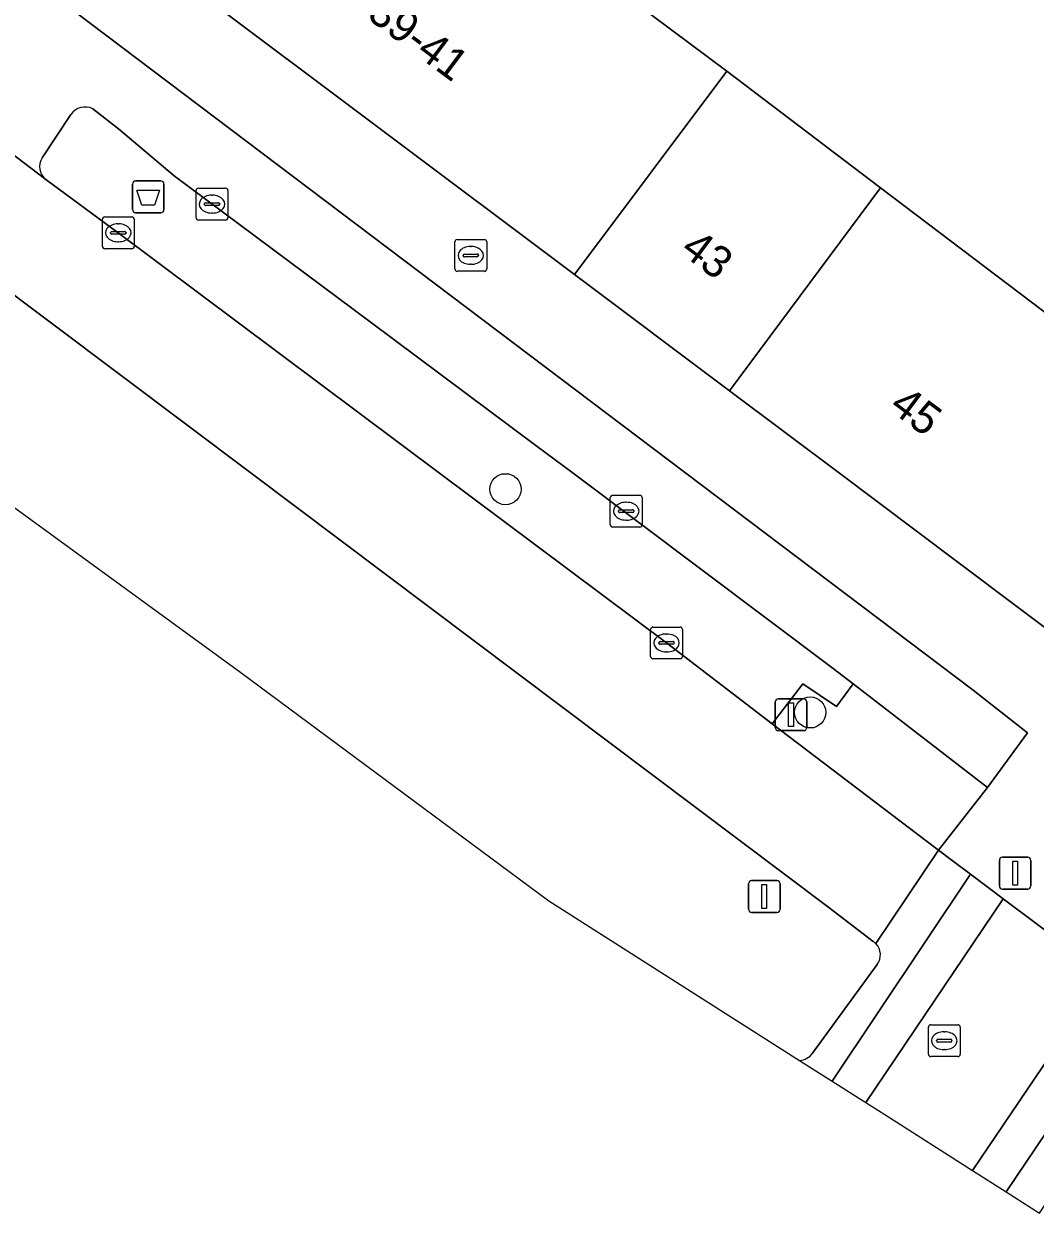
# Model space of a CAD drawing. Extents: x 161087 to 161926, y 382572 to 383873.
# Drawn here: x 161120.79 to 161152.56, y 383226.76 to 383264.12 of the extents above; entities that cross this region are included whole.
import ezdxf

# ---------------------------------------------------------------- set-up
doc = ezdxf.new("R2010")
doc.units = 0
for name, color, linetype in [('IMGEO_Afvalbak', 7, 'Continuous'), ('IMGEO_Berm_groen', 7, 'Continuous'), ('IMGEO_Berm_open', 7, 'Continuous'), ('IMGEO_Boom', 7, 'Continuous'), ('IMGEO_Brandkraan', 7, 'Continuous'), ('IMGEO_Fietspad_gesloten', 7, 'Continuous'), ('IMGEO_Kolk', 7, 'Continuous'), ('IMGEO_Lichtmast', 7, 'Continuous'), ('IMGEO_OVBaan_gesloten', 7, 'Continuous'), ('IMGEO_Pand', 7, 'Continuous'), ('IMGEO_Pand_nummerreeks', 7, 'Continuous'), ('IMGEO_Rijbaan_lokaal_gesloten', 7, 'Continuous'), ('IMGEO_Rijbaan_lokaal_open', 7, 'Continuous'), ('IMGEO_Rioolput', 7, 'Continuous'), ('IMGEO_Verkeerseiland_groen', 7, 'Continuous'), ('IMGEO_Verkeersregelinstallatiepaal', 7, 'Continuous'), ('IMGEO_Voetgangersgebied_open', 7, 'Continuous')]:
    doc.layers.add(name, color=color, linetype=linetype)

msp = doc.modelspace()

# ---------------------------------------------------------------- linework, layer by layer
at = {"layer": 'IMGEO_Afvalbak'}
for p, q in [((161124.206, 383258.282), (161124.206, 383259.082)), ((161124.206, 383259.082), (161124.206, 383258.282)), ((161124.306, 383259.182), (161125.096, 383259.182)), ((161125.096, 383259.182), (161124.306, 383259.182)), ((161125.196, 383259.082), (161125.196, 383258.282)), ((161125.196, 383258.282), (161125.196, 383259.082)), ((161125.096, 383258.182), (161124.306, 383258.182)), ((161124.306, 383258.182), (161125.096, 383258.182))]:
    msp.add_line(p, q, dxfattribs=at)
msp.add_lwpolyline([(161124.349, 383258.896), (161125.053, 383258.896), (161124.904, 383258.426), (161124.498, 383258.426), (161124.349, 383258.896)], dxfattribs=at)
for centre, start, end in [((161124.306, 383259.082), 90, 180), ((161124.306, 383259.082), 90, 180), ((161125.096, 383259.082), 0, 90), ((161125.096, 383259.082), 360, 90), ((161124.306, 383258.282), 180, 270), ((161124.306, 383258.282), 180, 270), ((161125.096, 383258.282), 270, 0), ((161125.096, 383258.282), 270, 0)]:
    msp.add_arc(centre, 0.1, start, end, dxfattribs=at)
at = {"layer": 'IMGEO_Berm_groen'}
msp.add_lwpolyline([(161146.845, 383243.381), (161146.322, 383242.671), (161145.266, 383243.39), (161144.303, 383242.133), (161149.136, 383238.449), (161149.525, 383238.158), (161151.057, 383240.133)], close=True, dxfattribs=at)
at = {"layer": 'IMGEO_Berm_open'}
for points in [[(161122.272, 383261.268), (161121.372, 383259.911)], [(161138.045, 383250), (161136.923, 383250.842), (161131.675, 383254.752), (161125.515, 383259.342), (161123.772, 383260.815), (161122.964, 383261.452)], [(161121.486, 383259.231), (161123.758, 383257.552), (161133.852, 383250), (161140.977, 383244.669), (161144.303, 383242.133), (161145.266, 383243.39), (161146.322, 383242.671), (161146.845, 383243.381), (161146.169, 383243.902), (161138.045, 383250)]]:
    msp.add_lwpolyline(points, dxfattribs=at)
for centre, radius, start, end in [((161122.728, 383260.947), 0.557, 64.9073, 144.8731), ((161121.801, 383259.633), 0.511, 147.0872, 231.9467)]:
    msp.add_arc(centre, radius, start, end, dxfattribs=at)
at = {"layer": 'IMGEO_Boom'}
for centre in [(161135.922, 383249.498), (161145.494, 383242.487)]:
    msp.add_circle(centre, 0.489, dxfattribs=at)
at = {"layer": 'IMGEO_Brandkraan'}
for p, q in [((161134.332, 383256.417), (161134.332, 383257.269)), ((161134.407, 383257.343), (161135.259, 383257.343)), ((161135.333, 383257.269), (161135.333, 383256.417)), ((161134.591, 383256.837), (161134.591, 383256.849)), ((161135.029, 383256.8), (161134.631, 383256.8)), ((161134.634, 383256.886), (161135.032, 383256.886)), ((161134.82, 383257.123), (161134.845, 383257.123)), ((161135.075, 383256.849), (161135.075, 383256.837)), ((161134.843, 383256.563), (161134.818, 383256.563)), ((161135.259, 383256.343), (161134.407, 383256.343))]:
    msp.add_line(p, q, dxfattribs=at)
for points in [[(161134.332, 383256.417), (161134.332, 383257.269)], [(161134.407, 383257.343), (161135.259, 383257.343)], [(161135.333, 383257.269), (161135.333, 383256.417)], [(161135.259, 383256.343), (161134.407, 383256.343)]]:
    msp.add_lwpolyline(points, dxfattribs=at)
for centre, radius, start, end in [((161134.409, 383257.267), 0.0765, 91.552, 178.448), ((161134.409, 383257.267), 0.0765, 91.552, 178.448), ((161135.257, 383257.267), 0.0765, 1.552, 88.448), ((161135.257, 383257.267), 0.0765, 1.552, 88.448), ((161134.631, 383256.846), 0.0403, 85.8775, 175.7526), ((161134.628, 383256.836), 0.0366, 178.938, 274.7102), ((161135.032, 383256.843), 0.043, 264.8664, 352.4533), ((161135.036, 383256.848), 0.0386, 1.7309, 96.639), ((161134.409, 383256.419), 0.0765, 181.552, 268.448), ((161134.409, 383256.419), 0.0765, 181.552, 268.448), ((161135.257, 383256.419), 0.0765, 271.552, 358.448), ((161135.257, 383256.419), 0.0765, 271.552, 358.448)]:
    msp.add_arc(centre, radius, start, end, dxfattribs=at)
for centre, major_axis, ratio, start_param, end_param in [((161134.819, 383256.843), (-0.387, 0.002), 0.722429, 4.712389, 7.853982), ((161134.844, 383256.843), (-0.39, 0.002), 0.717154, 1.570796, 4.712389)]:
    msp.add_ellipse(centre, major_axis=major_axis, ratio=ratio, start_param=start_param, end_param=end_param, dxfattribs=at)
at = {"layer": 'IMGEO_Fietspad_gesloten'}
for points in [[(161122.964, 383261.452), (161123.772, 383260.815), (161125.515, 383259.342), (161131.675, 383254.752), (161136.923, 383250.842), (161138.045, 383250), (161146.169, 383243.902), (161146.845, 383243.381), (161151.057, 383240.133), (161152.322, 383241.841), (161150.612, 383243.184), (161141.59, 383250), (161122.381, 383264.513)], [(161118.752, 383261.298), (161121.486, 383259.231)], [(161121.372, 383259.911), (161122.272, 383261.268)]]:
    msp.add_lwpolyline(points, dxfattribs=at)
for centre, radius, start, end in [((161122.728, 383260.947), 0.557, 64.9073, 144.8731), ((161121.801, 383259.633), 0.511, 147.0872, 231.9467)]:
    msp.add_arc(centre, radius, start, end, dxfattribs=at)
at = {"layer": 'IMGEO_Kolk'}
for p, q in [((161126.205, 383258.028), (161126.205, 383258.88)), ((161126.28, 383258.954), (161127.132, 383258.954)), ((161126.693, 383258.734), (161126.718, 383258.734)), ((161127.206, 383258.88), (161127.206, 383258.028)), ((161126.464, 383258.448), (161126.464, 383258.46)), ((161126.902, 383258.411), (161126.504, 383258.411)), ((161126.507, 383258.497), (161126.905, 383258.497)), ((161126.948, 383258.46), (161126.948, 383258.448)), ((161123.262, 383257.127), (161123.262, 383257.979)), ((161123.337, 383258.053), (161124.189, 383258.053)), ((161124.263, 383257.979), (161124.263, 383257.127)), ((161127.132, 383257.954), (161126.28, 383257.954)), ((161126.716, 383258.174), (161126.691, 383258.174)), ((161123.521, 383257.547), (161123.521, 383257.559)), ((161123.959, 383257.51), (161123.561, 383257.51)), ((161123.564, 383257.596), (161123.962, 383257.596)), ((161123.75, 383257.833), (161123.775, 383257.833)), ((161124.005, 383257.559), (161124.005, 383257.547)), ((161123.773, 383257.273), (161123.748, 383257.273)), ((161124.189, 383257.053), (161123.337, 383257.053)), ((161139.29, 383249.309), (161140.142, 383249.309)), ((161139.215, 383248.383), (161139.215, 383249.235)), ((161139.703, 383249.089), (161139.728, 383249.089)), ((161140.216, 383249.235), (161140.216, 383248.383)), ((161139.474, 383248.803), (161139.474, 383248.815)), ((161139.912, 383248.766), (161139.514, 383248.766)), ((161139.517, 383248.852), (161139.915, 383248.852)), ((161139.958, 383248.815), (161139.958, 383248.803)), ((161140.142, 383248.309), (161139.29, 383248.309)), ((161139.726, 383248.529), (161139.701, 383248.529)), ((161140.481, 383244.244), (161140.481, 383245.096)), ((161140.556, 383245.17), (161141.408, 383245.17)), ((161140.969, 383244.95), (161140.994, 383244.95)), ((161141.482, 383245.096), (161141.482, 383244.244)), ((161140.74, 383244.664), (161140.74, 383244.676)), ((161141.178, 383244.627), (161140.78, 383244.627)), ((161140.783, 383244.713), (161141.181, 383244.713)), ((161141.224, 383244.676), (161141.224, 383244.664)), ((161141.408, 383244.17), (161140.556, 383244.17)), ((161140.992, 383244.39), (161140.967, 383244.39))]:
    msp.add_line(p, q, dxfattribs=at)
for points in [[(161126.205, 383258.028), (161126.205, 383258.88)], [(161126.28, 383258.954), (161127.132, 383258.954)], [(161127.206, 383258.88), (161127.206, 383258.028)], [(161123.262, 383257.127), (161123.262, 383257.979)], [(161123.337, 383258.053), (161124.189, 383258.053)], [(161124.263, 383257.979), (161124.263, 383257.127)], [(161127.132, 383257.954), (161126.28, 383257.954)], [(161124.189, 383257.053), (161123.337, 383257.053)], [(161139.29, 383249.309), (161140.142, 383249.309)], [(161139.215, 383248.383), (161139.215, 383249.235)], [(161140.216, 383249.235), (161140.216, 383248.383)], [(161140.142, 383248.309), (161139.29, 383248.309)], [(161140.481, 383244.244), (161140.481, 383245.096)], [(161140.556, 383245.17), (161141.408, 383245.17)], [(161141.482, 383245.096), (161141.482, 383244.244)], [(161141.408, 383244.17), (161140.556, 383244.17)]]:
    msp.add_lwpolyline(points, dxfattribs=at)
for centre, radius, start, end in [((161126.282, 383258.878), 0.0765, 91.552, 178.448), ((161126.282, 383258.878), 0.0765, 91.552, 178.448), ((161127.13, 383258.878), 0.0765, 1.552, 88.448), ((161127.13, 383258.878), 0.0765, 1.552, 88.448), ((161126.504, 383258.457), 0.0403, 85.8775, 175.7526), ((161126.501, 383258.447), 0.0366, 178.938, 274.7102), ((161126.905, 383258.454), 0.043, 264.8664, 352.4533), ((161126.909, 383258.459), 0.0386, 1.7309, 96.639), ((161123.339, 383257.977), 0.0765, 91.552, 178.448), ((161123.339, 383257.977), 0.0765, 91.552, 178.448), ((161124.187, 383257.977), 0.0765, 1.552, 88.448), ((161124.187, 383257.977), 0.0765, 1.552, 88.448), ((161126.282, 383258.03), 0.0765, 181.552, 268.448), ((161126.282, 383258.03), 0.0765, 181.552, 268.448), ((161127.13, 383258.03), 0.0765, 271.552, 358.448), ((161127.13, 383258.03), 0.0765, 271.552, 358.448), ((161123.561, 383257.556), 0.0403, 85.8775, 175.7526), ((161123.558, 383257.546), 0.0366, 178.938, 274.7102), ((161123.962, 383257.553), 0.043, 264.8664, 352.4533), ((161123.966, 383257.558), 0.0386, 1.7309, 96.639), ((161123.339, 383257.129), 0.0765, 181.552, 268.448), ((161123.339, 383257.129), 0.0765, 181.552, 268.448), ((161124.187, 383257.129), 0.0765, 271.552, 358.448), ((161124.187, 383257.129), 0.0765, 271.552, 358.448), ((161139.292, 383249.233), 0.0765, 91.552, 178.448), ((161139.292, 383249.233), 0.0765, 91.552, 178.448), ((161140.14, 383249.233), 0.0765, 1.552, 88.448), ((161140.14, 383249.233), 0.0765, 1.552, 88.448), ((161139.514, 383248.812), 0.0403, 85.8775, 175.7526), ((161139.511, 383248.802), 0.0366, 178.938, 274.7102), ((161139.915, 383248.809), 0.043, 264.8664, 352.4533), ((161139.919, 383248.814), 0.0386, 1.7309, 96.639), ((161139.292, 383248.385), 0.0765, 181.552, 268.448), ((161139.292, 383248.385), 0.0765, 181.552, 268.448), ((161140.14, 383248.385), 0.0765, 271.552, 358.448), ((161140.14, 383248.385), 0.0765, 271.552, 358.448), ((161140.558, 383245.094), 0.0765, 91.552, 178.448), ((161140.558, 383245.094), 0.0765, 91.552, 178.448), ((161141.406, 383245.094), 0.0765, 1.552, 88.448), ((161141.406, 383245.094), 0.0765, 1.552, 88.448), ((161140.78, 383244.673), 0.0403, 85.8775, 175.7526), ((161140.777, 383244.663), 0.0366, 178.938, 274.7102), ((161141.181, 383244.67), 0.043, 264.8664, 352.4533), ((161141.185, 383244.675), 0.0386, 1.7309, 96.639), ((161140.558, 383244.246), 0.0765, 181.552, 268.448), ((161140.558, 383244.246), 0.0765, 181.552, 268.448), ((161141.406, 383244.246), 0.0765, 271.552, 358.448), ((161141.406, 383244.246), 0.0765, 271.552, 358.448)]:
    msp.add_arc(centre, radius, start, end, dxfattribs=at)
for centre, major_axis, ratio, start_param, end_param in [((161126.692, 383258.454), (-0.387, 0.002), 0.722429, 4.712389, 7.853982), ((161126.717, 383258.454), (-0.39, 0.002), 0.717154, 1.570796, 4.712389), ((161123.749, 383257.553), (-0.387, 0.002), 0.722429, 4.712389, 7.853982), ((161123.774, 383257.553), (-0.39, 0.002), 0.717154, 1.570796, 4.712389), ((161139.702, 383248.809), (-0.387, 0.002), 0.722429, 4.712389, 7.853982), ((161139.727, 383248.809), (-0.39, 0.002), 0.717154, 1.570796, 4.712389), ((161140.968, 383244.67), (-0.387, 0.002), 0.722429, 4.712389, 7.853982), ((161140.993, 383244.67), (-0.39, 0.002), 0.717154, 1.570796, 4.712389)]:
    msp.add_ellipse(centre, major_axis=major_axis, ratio=ratio, start_param=start_param, end_param=end_param, dxfattribs=at)
at = {"layer": 'IMGEO_Lichtmast'}
for p, q in [((161144.397, 383242.016), (161144.397, 383242.816)), ((161144.397, 383242.816), (161144.397, 383242.016)), ((161144.497, 383242.916), (161145.287, 383242.916)), ((161145.287, 383242.916), (161144.497, 383242.916)), ((161145.387, 383242.816), (161145.387, 383242.016)), ((161145.387, 383242.016), (161145.387, 383242.816)), ((161145.287, 383241.916), (161144.497, 383241.916)), ((161144.497, 383241.916), (161145.287, 383241.916))]:
    msp.add_line(p, q, dxfattribs=at)
msp.add_lwpolyline([(161144.817, 383242.791), (161144.967, 383242.791), (161144.967, 383242.041), (161144.817, 383242.041), (161144.817, 383242.791)], dxfattribs=at)
for centre, start, end in [((161144.497, 383242.816), 90, 180), ((161144.497, 383242.816), 90, 180), ((161145.287, 383242.816), 0, 90), ((161145.287, 383242.816), 360, 90), ((161144.497, 383242.016), 180, 270), ((161144.497, 383242.016), 180, 270), ((161145.287, 383242.016), 270, 0), ((161145.287, 383242.016), 270, 0)]:
    msp.add_arc(centre, 0.1, start, end, dxfattribs=at)
at = {"layer": 'IMGEO_OVBaan_gesloten'}
for points in [[(161133.852, 383250), (161123.758, 383257.552), (161121.486, 383259.231), (161118.752, 383261.298), (161116.847, 383258.357), (161119.591, 383256.269), (161127.932, 383250), (161146.078, 383236.362), (161147.473, 383235.291)], [(161147.554, 383235.225), (161149.525, 383238.158), (161149.136, 383238.449), (161144.303, 383242.133), (161140.977, 383244.669), (161133.852, 383250)]]:
    msp.add_lwpolyline(points, dxfattribs=at)
msp.add_arc((161147.169, 383234.835), 0.548, 45.3513, 56.3014, dxfattribs=at)
at = {"layer": 'IMGEO_Pand'}
for points in [[(161140.496, 383278.979), (161132.96, 383270.029), (161142.873, 383262.631), (161147.705, 383258.97), (161159.381, 383250.122), (161165.893, 383257.765)], [(161138.093, 383256.246), (161142.873, 383262.631), (161132.96, 383270.029), (161130.831, 383271.64), (161126.05, 383265.285)], [(161138.093, 383256.246), (161142.959, 383252.594), (161147.705, 383258.97), (161142.873, 383262.631)], [(161147.705, 383258.97), (161142.959, 383252.594), (161146.415, 383250), (161150.046, 383247.275), (161154.26, 383244.112), (161159.277, 383250), (161159.381, 383250.122)]]:
    msp.add_lwpolyline(points, close=True, dxfattribs=at)
at = {"layer": 'IMGEO_Rijbaan_lokaal_gesloten'}
for points in [[(161147.239, 383230.234), (161151.558, 383236.634), (161150.529, 383237.405), (161146.183, 383230.906)], [(161151.648, 383227.424), (161155.741, 383233.5), (161154.75, 383234.243), (161150.587, 383228.1)]]:
    msp.add_lwpolyline(points, close=True, dxfattribs=at)
at = {"layer": 'IMGEO_Rijbaan_lokaal_open'}
for points in [[(161146.183, 383230.906), (161150.529, 383237.405), (161149.954, 383237.836), (161149.525, 383238.158), (161147.554, 383235.225)], [(161147.595, 383234.572), (161145.567, 383231.787)], [(161145.159, 383231.558), (161146.183, 383230.906)]]:
    msp.add_lwpolyline(points, dxfattribs=at)
for points in [[(161150.587, 383228.1), (161154.75, 383234.243), (161151.558, 383236.634), (161147.239, 383230.234), (161147.834, 383229.855)], [(161152.697, 383226.756), (161154.382, 383229.266), (161156.728, 383232.76), (161155.741, 383233.5), (161151.648, 383227.424)]]:
    msp.add_lwpolyline(points, close=True, dxfattribs=at)
for centre, radius, start, end in [((161147.203, 383234.875), 0.496, 322.2839, 44.9015), ((161145.143, 383232.064), 0.507, 271.858, 326.8429)]:
    msp.add_arc(centre, radius, start, end, dxfattribs=at)
at = {"layer": 'IMGEO_Rioolput'}
for p, q in [((161149.204, 383231.749), (161149.204, 383232.601)), ((161149.279, 383232.675), (161150.131, 383232.675)), ((161150.205, 383232.601), (161150.205, 383231.749)), ((161149.463, 383232.169), (161149.463, 383232.181)), ((161149.901, 383232.132), (161149.503, 383232.132)), ((161149.506, 383232.218), (161149.904, 383232.218)), ((161149.692, 383232.455), (161149.717, 383232.455)), ((161149.947, 383232.181), (161149.947, 383232.169)), ((161149.715, 383231.895), (161149.69, 383231.895)), ((161150.131, 383231.675), (161149.279, 383231.675))]:
    msp.add_line(p, q, dxfattribs=at)
for points in [[(161149.204, 383231.749), (161149.204, 383232.601)], [(161149.279, 383232.675), (161150.131, 383232.675)], [(161150.205, 383232.601), (161150.205, 383231.749)], [(161150.131, 383231.675), (161149.279, 383231.675)]]:
    msp.add_lwpolyline(points, dxfattribs=at)
for centre, radius, start, end in [((161149.281, 383232.599), 0.0765, 91.552, 178.448), ((161149.281, 383232.599), 0.0765, 91.552, 178.448), ((161150.129, 383232.599), 0.0765, 1.552, 88.448), ((161150.129, 383232.599), 0.0765, 1.552, 88.448), ((161149.503, 383232.178), 0.0403, 85.8775, 175.7526), ((161149.5, 383232.168), 0.0366, 178.938, 274.7102), ((161149.904, 383232.175), 0.043, 264.8664, 352.4533), ((161149.908, 383232.18), 0.0386, 1.7309, 96.639), ((161149.281, 383231.751), 0.0765, 181.552, 268.448), ((161149.281, 383231.751), 0.0765, 181.552, 268.448), ((161150.129, 383231.751), 0.0765, 271.552, 358.448), ((161150.129, 383231.751), 0.0765, 271.552, 358.448)]:
    msp.add_arc(centre, radius, start, end, dxfattribs=at)
for centre, major_axis, ratio, start_param, end_param in [((161149.691, 383232.175), (-0.387, 0.002), 0.722429, 4.712389, 7.853982), ((161149.716, 383232.175), (-0.39, 0.002), 0.717154, 1.570796, 4.712389)]:
    msp.add_ellipse(centre, major_axis=major_axis, ratio=ratio, start_param=start_param, end_param=end_param, dxfattribs=at)
at = {"layer": 'IMGEO_Verkeerseiland_groen'}
for points in [[(161147.473, 383235.291), (161146.078, 383236.362), (161127.932, 383250), (161119.591, 383256.269)], [(161116.722, 383251.833), (161117.848, 383250.848), (161127.61, 383243.743), (161137.284, 383236.571), (161145.159, 383231.558)], [(161145.567, 383231.787), (161147.595, 383234.572)]]:
    msp.add_lwpolyline(points, dxfattribs=at)
for centre, radius, start, end in [((161147.169, 383234.835), 0.548, 45.3513, 56.3014), ((161147.203, 383234.875), 0.496, 322.2839, 44.9015), ((161145.143, 383232.064), 0.507, 271.858, 326.8429)]:
    msp.add_arc(centre, radius, start, end, dxfattribs=at)
at = {"layer": 'IMGEO_Verkeersregelinstallatiepaal'}
for p, q in [((161151.434, 383237.035), (161151.434, 383237.835)), ((161151.434, 383237.835), (161151.434, 383237.035)), ((161151.534, 383237.935), (161152.324, 383237.935)), ((161152.324, 383237.935), (161151.534, 383237.935)), ((161152.424, 383237.835), (161152.424, 383237.035)), ((161152.424, 383237.035), (161152.424, 383237.835)), ((161143.555, 383236.307), (161143.555, 383237.107)), ((161143.555, 383237.107), (161143.555, 383236.307)), ((161143.655, 383237.207), (161144.445, 383237.207)), ((161144.445, 383237.207), (161143.655, 383237.207)), ((161144.545, 383237.107), (161144.545, 383236.307)), ((161144.545, 383236.307), (161144.545, 383237.107)), ((161152.324, 383236.935), (161151.534, 383236.935)), ((161151.534, 383236.935), (161152.324, 383236.935)), ((161144.445, 383236.207), (161143.655, 383236.207)), ((161143.655, 383236.207), (161144.445, 383236.207))]:
    msp.add_line(p, q, dxfattribs=at)
for points in [[(161151.854, 383237.81), (161152.004, 383237.81), (161152.004, 383237.06), (161151.854, 383237.06), (161151.854, 383237.81)], [(161143.975, 383237.082), (161144.125, 383237.082), (161144.125, 383236.332), (161143.975, 383236.332), (161143.975, 383237.082)]]:
    msp.add_lwpolyline(points, dxfattribs=at)
for centre, start, end in [((161151.534, 383237.835), 90, 180), ((161151.534, 383237.835), 90, 180), ((161152.324, 383237.835), 0, 90), ((161152.324, 383237.835), 360, 90), ((161143.655, 383237.107), 90, 180), ((161143.655, 383237.107), 90, 180), ((161144.445, 383237.107), 0, 90), ((161144.445, 383237.107), 360, 90), ((161151.534, 383237.035), 180, 270), ((161151.534, 383237.035), 180, 270), ((161152.324, 383237.035), 270, 0), ((161152.324, 383237.035), 270, 0), ((161143.655, 383236.307), 180, 270), ((161143.655, 383236.307), 180, 270), ((161144.445, 383236.307), 270, 0), ((161144.445, 383236.307), 270, 0)]:
    msp.add_arc(centre, 0.1, start, end, dxfattribs=at)
at = {"layer": 'IMGEO_Voetgangersgebied_open'}
for points in [[(161154.26, 383244.112), (161150.046, 383247.275), (161146.415, 383250), (161142.959, 383252.594), (161138.093, 383256.246), (161126.05, 383265.285)], [(161122.381, 383264.513), (161141.59, 383250), (161150.612, 383243.184), (161152.322, 383241.841), (161151.057, 383240.133), (161149.525, 383238.158), (161149.954, 383237.836), (161150.529, 383237.405), (161151.558, 383236.634), (161154.75, 383234.243), (161155.741, 383233.5), (161156.728, 383232.76), (161158.075, 383234.534), (161159.37, 383236.191), (161160.512, 383235.259), (161164.804, 383231.635)]]:
    msp.add_lwpolyline(points, dxfattribs=at)

# ---------------------------------------------------------------- texts
at = {"layer": 'IMGEO_Pand_nummerreeks'}
for s, rotation, p in [('39-41', 323.1106, (161131.533, 383264.32)), ('43', 323.1106, (161141.377, 383256.932)), ('45', 323.1108, (161147.934, 383252.011))]:
    msp.add_text(s, height=1, rotation=rotation, dxfattribs=at).set_placement(p)

doc.saveas('drawing.dxf')
